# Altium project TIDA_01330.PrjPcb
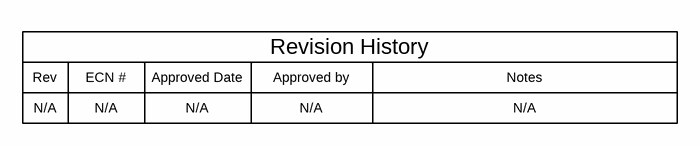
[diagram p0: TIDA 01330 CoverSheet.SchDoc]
CopyrightYear: 2016; EVM_Orderable: N/A; PCB_Rev: E1; PRJ_Customer: Public Release; PRJ_Engineer: Clark Kinnaird; PRJ_Number: TIDA-01330; PRJ_Title: Automotive 2-Axis Power Seat Driver; SCH_Rev: E1; TechSupport: http://www.ti.com/support; TID: TIDA-01330
3 sheets, 85 parts. Net scope: global (net labels, ports and power ports of the same name join across sheets).
Board file: TIDA-01330.PcbDoc
Sheets:
  TIDA 01330 CoverSheet.SchDoc
  TIDA 01330 Schematic.SchDoc
  TID_Hardware.SchDoc

## Sheet TIDA 01330 CoverSheet.SchDoc
size 431 x 279 mm; Date: Not shown in title block; ApprovedBy: Not shown in title block; CheckedBy: Not shown in title block; Author: Not shown in title block; CompanyName: Not shown in title block; Engineer: Not shown in title block; Organization: Not shown in title block; Address1: Not shown in title block; Address2: Not shown in title block; Address3: Not shown in title block; Address4: Not shown in title block; DocumentNumber: 1; Revision: Use project parameter SCH_Rev; SheetNumber: 1; SheetTotal: 3; PageSetup: Record=PageOptions¦CenterHorizontal=True¦CenterVertical=True¦PrintScale=1.00¦XCorrection=1.00¦YCorrection=1.00¦PrintKind=0¦BorderSize=5000000¦LeftOffset=0¦BottomOffset=0¦Orientation=2¦PaperLength=1000¦PaperWidth=1000¦Scale=100¦PaperSource=15¦PrintQuality=600¦MediaType=1¦DitherType=10¦PaperKind=Letter¦PrintScaleMode=1

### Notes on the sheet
- Rev
- N/A
- ECN #
- Approved Date
- Approved by
- Revision History
- Notes

## Sheet TIDA 01330 Schematic.SchDoc
size 431 x 279 mm; Date: Not shown in title block; ApprovedBy: Not shown in title block; CheckedBy: Not shown in title block; Author: Not shown in title block; CompanyName: Not shown in title block; Engineer: Not shown in title block; Organization: Not shown in title block; Address1: Not shown in title block; Address2: Not shown in title block; Address3: Not shown in title block; Address4: Not shown in title block; DocumentNumber: 1; Revision: Use project parameter SCH_Rev; SheetNumber: 2; SheetTotal: 2; PageSetup: Record=PageOptions¦CenterHorizontal=True¦CenterVertical=True¦PrintScale=0.98¦XCorrection=1.00¦YCorrection=1.00¦PrintKind=0¦BorderSize=5000000¦LeftOffset=0¦BottomOffset=0¦Orientation=2¦PaperLength=4318¦PaperWidth=2794¦Scale=100¦PaperSource=15¦PrintQuality=-3¦MediaType=1¦DitherType=10¦PrintScaleMode=1¦PaperKind=11x17¦PaperIndex=17
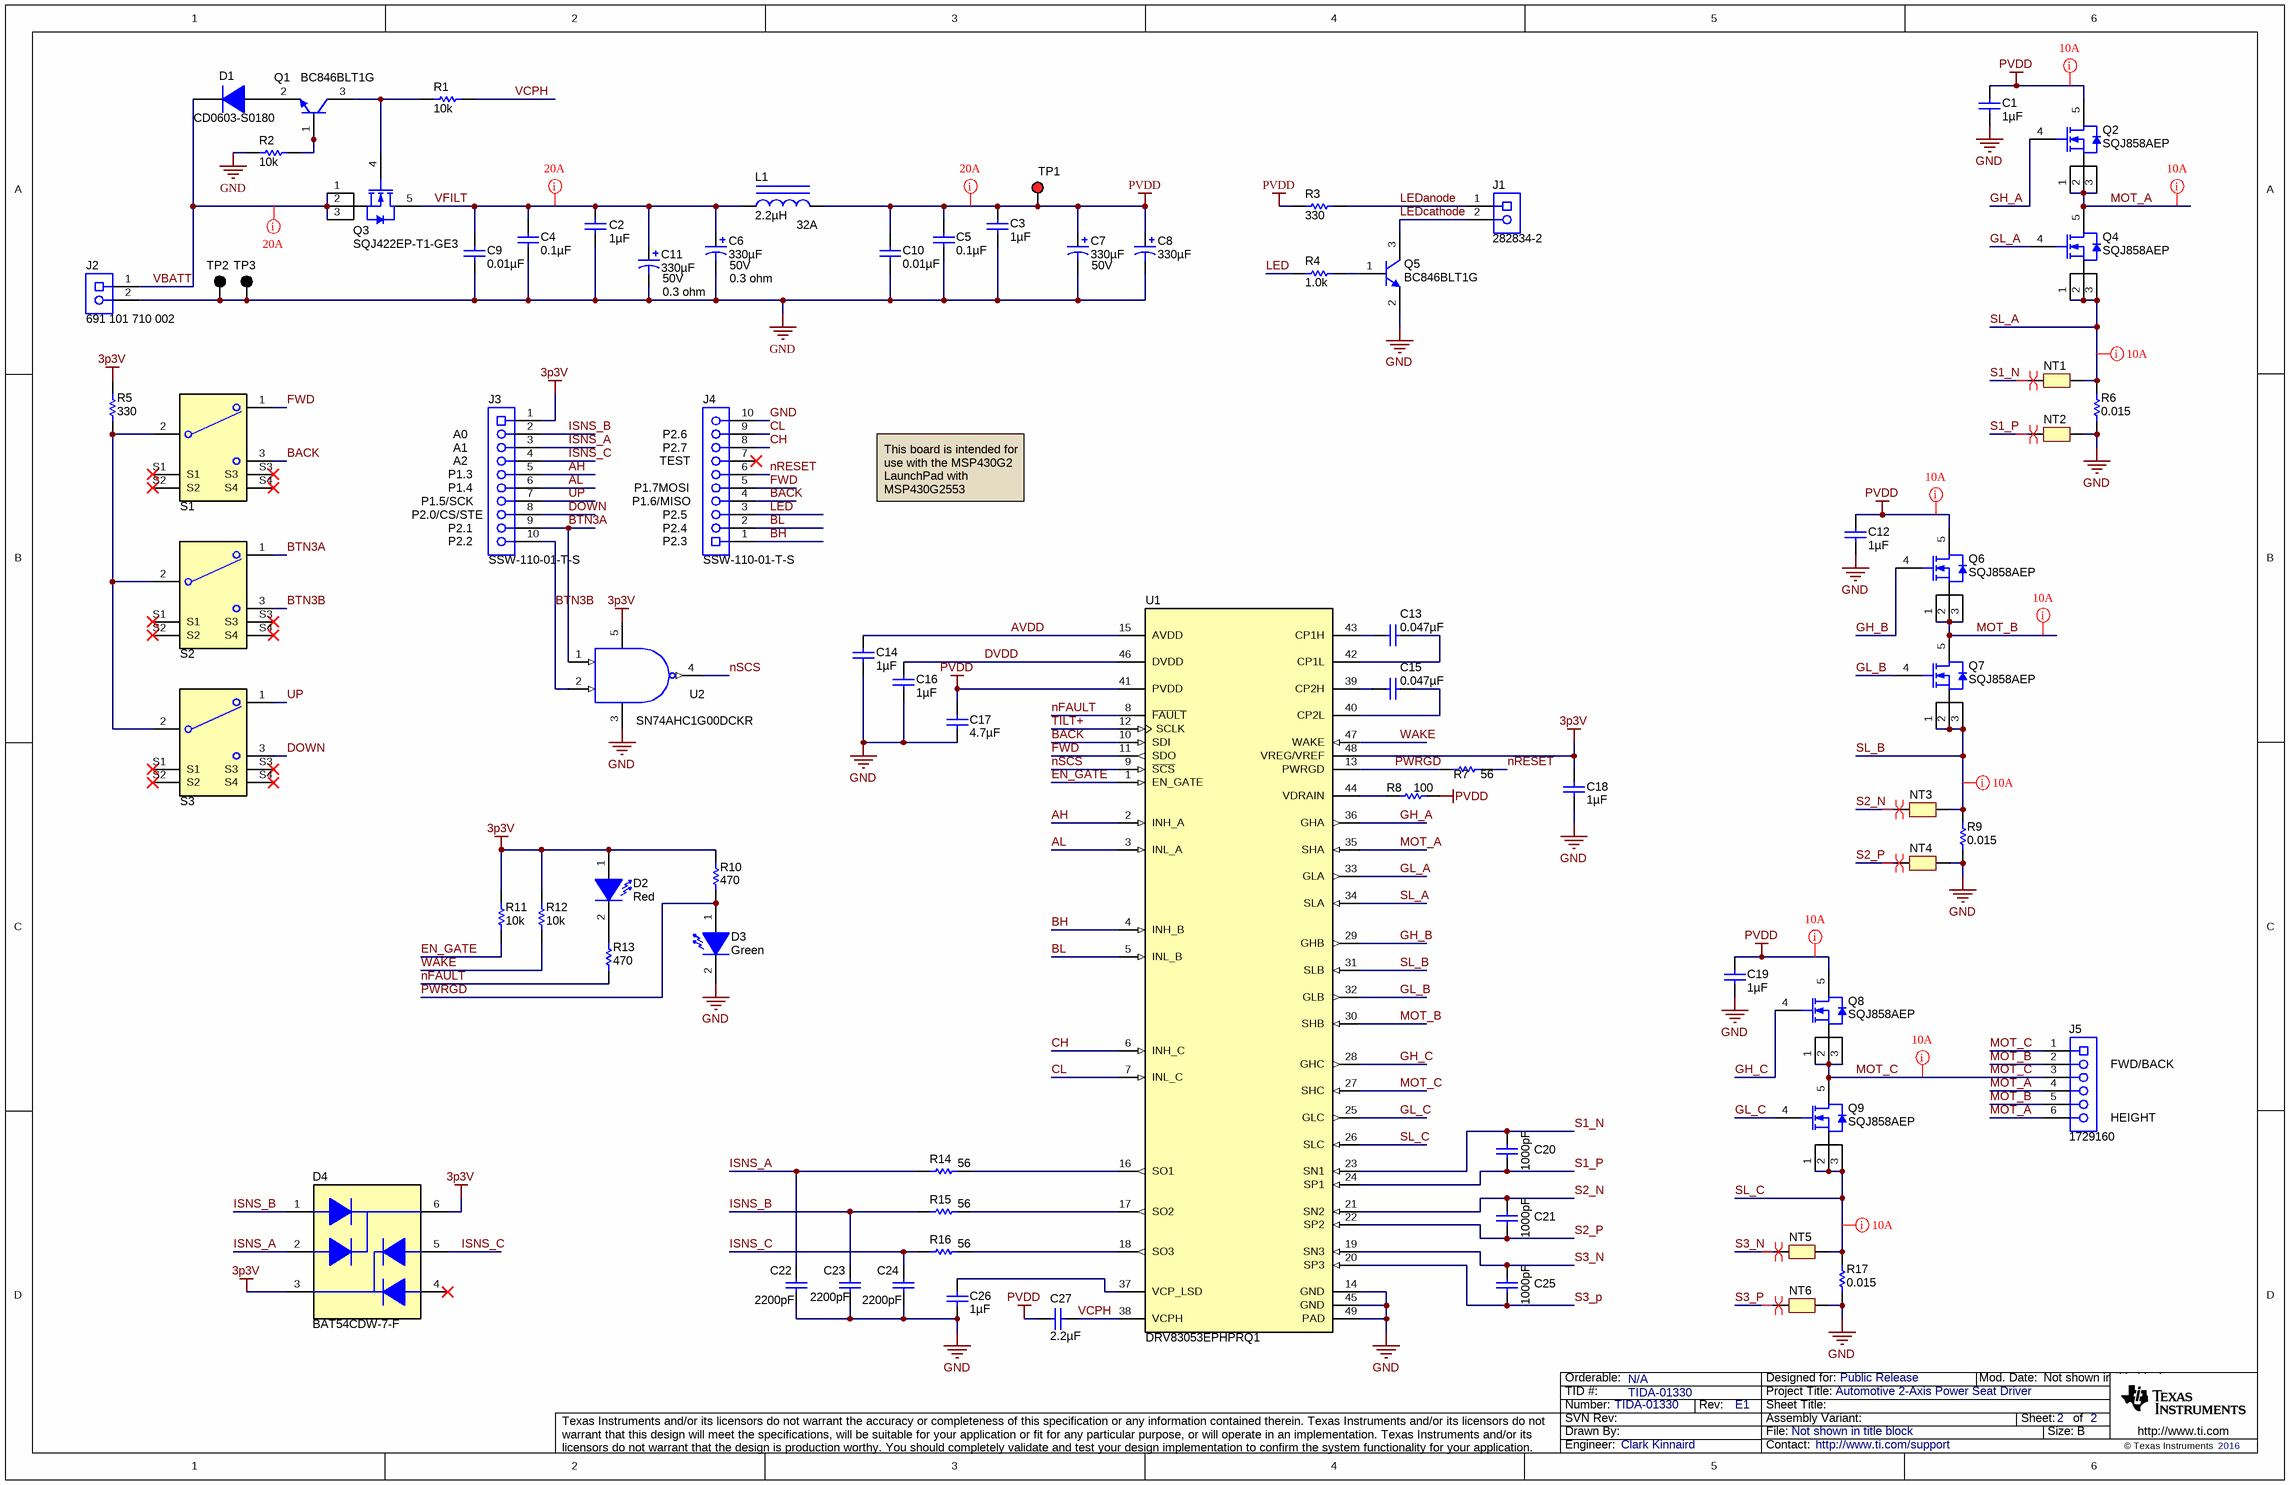
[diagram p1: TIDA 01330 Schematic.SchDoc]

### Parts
C1  ValueDisplayed: 1µF  [0603L]  (hidden comment: UMK107AB7105KA-T)
C2  ValueDisplayed: 1µF  [0805L]  (hidden comment: GRM21BR71H105KA12L)
C3  ValueDisplayed: 1µF  [0805L]  (hidden comment: GRM21BR71H105KA12L)
C4  ValueDisplayed: 0.1µF  [0603]  (hidden comment: C1608X7R1H104K080AA)
C5  ValueDisplayed: 0.1µF  [0603]  (hidden comment: C1608X7R1H104K080AA)
C6  ValueDisplayed: 330µF  Value1: 0.3 ohm  Value2: 50V  [SM_RADIAL_G]  (hidden comment: EEE-FT1H331AP)
C7  ValueDisplayed: 330µF  Value2: 50V  [SM_RADIAL_G]  (hidden comment: EEE-FT1H331AP)
C8  ValueDisplayed: 330µF  [SM_RADIAL_G]  (hidden comment: EEE-FT1H331AP)
C9  ValueDisplayed: 0.01µF  [0603]  (hidden comment: C1608X7R1H103K080AA)
C10  ValueDisplayed: 0.01µF  [0603]  (hidden comment: C1608X7R1H103K080AA)
C11  ValueDisplayed: 330µF  Value1: 0.3 ohm  Value2: 50V  [SM_RADIAL_G]  (hidden comment: EEE-FT1H331AP)
C12  ValueDisplayed: 1µF  [0603L]  (hidden comment: UMK107AB7105KA-T)
C13  ValueDisplayed: 0.047µF  [0603L]  (hidden comment: C0603C473K1RACTU)
C14  ValueDisplayed: 1µF  [0603]  (hidden comment: C1608X7R1C105K080AC)
C15  ValueDisplayed: 0.047µF  [0603L]  (hidden comment: C0603C473K1RACTU)
C16  ValueDisplayed: 1µF  [0603]  (hidden comment: C1608X7R1C105K080AC)
C17  ValueDisplayed: 4.7µF  [1206_180]  (hidden comment: GRM31CR71H475KA12L)
C18  ValueDisplayed: 1µF  [0603]  (hidden comment: C1608X7R1C105K080AC)
C19  ValueDisplayed: 1µF  [0603L]  (hidden comment: UMK107AB7105KA-T)
C20  ValueDisplayed: 1000pF  [0603L]  (hidden comment: GRM188R71C102KA01D)
C21  ValueDisplayed: 1000pF  [0603L]  (hidden comment: GRM188R71C102KA01D)
C22  ValueDisplayed: 2200pF  [0603L]  (hidden comment: GRM188R71C222KA01D)
C23  ValueDisplayed: 2200pF  [0603L]  (hidden comment: GRM188R71C222KA01D)
C24  ValueDisplayed: 2200pF  [0603L]  (hidden comment: GRM188R71C222KA01D)
C25  ValueDisplayed: 1000pF  [0603L]  (hidden comment: GRM188R71C102KA01D)
C26  ValueDisplayed: 1µF  [0603]  (hidden comment: C1608X7R1C105K080AC)
C27  ValueDisplayed: 2.2µF  [1210_270]  (hidden comment: GRM32ER72A225KA35L)
D1  CD0603-S0180  [Diode_0603]
D2  value Red  [LED_LTST-C170_Red]  (hidden comment: LTST-C170KRKT)
D3  value Green  [LTST-C170KGKT_Green]  (hidden comment: LTST-C170KGKT)
D4  BAT54CDW-7-F  [SOT-363]
J1  282834-2  [TEC_282834-2]
J2  691 101 710 002  [Wurth_691101710002]
J3  SSW-110-01-T-S  [Samtec_SSW-110-x1-x-S]
J4  SSW-110-01-T-S  [Samtec_SSW-110-x1-x-S]
J5  1729160  [Phoenix_1729160]
L1  ValueDisplayed: 2.2µH  Value2: 32A  [XAL1010]  (hidden comment: XAL1010-222MEB)
NT1  Net-Tie  [Net-Tie_10mil]  (value not drawn)  (net tie, no BOM)
NT2  Net-Tie  [Net-Tie_10mil]  (value not drawn)  (net tie, no BOM)
NT3  Net-Tie  [Net-Tie_10mil]  (value not drawn)  (net tie, no BOM)
NT4  Net-Tie  [Net-Tie_10mil]  (value not drawn)  (net tie, no BOM)
NT5  Net-Tie  [Net-Tie_10mil]  (value not drawn)  (net tie, no BOM)
NT6  Net-Tie  [Net-Tie_10mil]  (value not drawn)  (net tie, no BOM)
Q1  BC846BLT1G  [SOT-23]
Q2  SQJ858AEP  [PowerPAK_SO-8L]
Q3  SQJ422EP-T1-GE3  [PowerPAK_SO-8L]
Q4  SQJ858AEP  [PowerPAK_SO-8L]
Q5  BC846BLT1G  [SOT-23]
Q6  SQJ858AEP  [PowerPAK_SO-8L]
Q7  SQJ858AEP  [PowerPAK_SO-8L]
Q8  SQJ858AEP  [PowerPAK_SO-8L]
Q9  SQJ858AEP  [PowerPAK_SO-8L]
R1  ValueDisplayed: 10k  [0402]  (hidden comment: CRCW040210K0JNED)
R2  ValueDisplayed: 10k  [0402]  (hidden comment: CRCW040210K0JNED)
R3  ValueDisplayed: 330  [1206]  (hidden comment: CRCW1206330RJNEA)
R4  ValueDisplayed: 1.0k  [0402]  (hidden comment: CRCW04021K00JNED)
R5  ValueDisplayed: 330  [0402]  (hidden comment: CRCW0402330RJNED)
R6  ValueDisplayed: 0.015  [2512]  (hidden comment: CRA2512-FZ-R015ELF)
R7  ValueDisplayed: 56  [0402]  (hidden comment: CRCW040256R0JNED)
R8  ValueDisplayed: 100  [0402]  (hidden comment: CRCW0402100RFKED)
R9  ValueDisplayed: 0.015  [2512]  (hidden comment: CRA2512-FZ-R015ELF)
R10  ValueDisplayed: 470  [0402]  (hidden comment: CRCW0402470RJNED)
R11  ValueDisplayed: 10k  [0402]  (hidden comment: CRCW040210K0JNED)
R12  ValueDisplayed: 10k  [0402]  (hidden comment: CRCW040210K0JNED)
R13  ValueDisplayed: 470  [0402]  (hidden comment: CRCW0402470RJNED)
R14  ValueDisplayed: 56  [0402]  (hidden comment: CRCW040256R0JNED)
R15  ValueDisplayed: 56  [0402]  (hidden comment: CRCW040256R0JNED)
R16  ValueDisplayed: 56  [0402]  (hidden comment: CRCW040256R0JNED)
R17  ValueDisplayed: 0.015  [2512]  (hidden comment: CRA2512-FZ-R015ELF)
S1  7105J3V3QE2  [SW_710XJ3V3]  (value not drawn)
S2  7105J3V3QE2  [SW_710XJ3V3]  (value not drawn)
S3  7105J3V3QE2  [SW_710XJ3V3]  (value not drawn)
TP1  5005  [Keystone5005]  (value not drawn)
TP2  5006  [Keystone5006]  (value not drawn)
TP3  5006  [Keystone5006]  (value not drawn)
U1  DRV83053EPHPRQ1  [PHP0048G_N]
U2  SN74AHC1G00DCKR  [DCK0005A_N]

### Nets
3p3V: C18.2 D2.1(A) D4.3(C2) D4.6(C1) J3.1 R5.1 R10.2 R11.2 R12.2 U1.48(VREG/VREF) U2.5(VCC)
GND: C1.2 C2.2 C3.2 C4.2 C5.2 C6.2(-) C7.2(-) C8.2(-) C9.2 C10.2 C11.2(-) C12.2 C14.1 C16.1 C17.2 C18.1 C19.2 C22.2 C23.2 C24.2 C26.2 D3.2(K) J2.2 J4.10 NT2.2 NT4.2 NT6.2 Q5.2(E) R2.2 R6.1 R9.1 R17.1 TP2.1 TP3.1 U1.14(GND) U1.45(GND) U1.49(PAD) U2.3(GND)
PVDD: C1.1 C3.1 C5.1 C7.1(+) C8.1(+) C10.1 C12.1 C17.1 C19.1 C27.2 L1.2 Q2.5(D) Q6.5(D) Q8.5(D) R3.1 R8.2 TP1.1 U1.41(PVDD)
AH: J3.5 U1.2(INH_A)
AL: J3.6 U1.3(INL_A)
AVDD: C14.2 U1.15(AVDD)
BACK: J4.4 S1.3 U1.10(SDI)
BH: J4.1 U1.4(INH_B)
BL: J4.2 U1.5(INL_B)
BTN3A: J3.9 S2.1 U2.1(A)
BTN3B: J3.10 S2.3 U2.2(B)
CH: J4.8 U1.6(INH_C)
CL: J4.9 U1.7(INL_C)
DOWN: J3.8 S3.3
DVDD: C16.2 U1.46(DVDD)
EN_GATE: R11.1 U1.1(EN_GATE)
FWD: J4.5 S1.1 U1.11(SDO)
GH_A: Q2.4(G) U1.36(GHA)
GH_B: Q6.4(G) U1.29(GHB)
GH_C: Q8.4(G) U1.28(GHC)
GL_A: Q4.4(G) U1.33(GLA)
GL_B: Q7.4(G) U1.32(GLB)
GL_C: Q9.4(G) U1.25(GLC)
ISNS_A: C22.1 D4.2(A1) J3.3 R14.1
ISNS_B: C23.1 D4.1(A1) J3.2 R15.1
ISNS_C: C24.1 D4.5(A2) J3.4 R16.1
LED: J4.3 R4.1
LEDanode: J1.1 R3.2
LEDcathode: J1.2 Q5.3(C)
MOT_A: J5.4 J5.6 Q2.1(S) Q2.2(S) Q2.3(S) Q4.5(D) U1.35(SHA)
MOT_B: J5.2 J5.5 Q6.1(S) Q6.2(S) Q6.3(S) Q7.5(D) U1.30(SHB)
MOT_C: J5.1 J5.3 Q8.1(S) Q8.2(S) Q8.3(S) Q9.5(D) U1.27(SHC)
nFAULT: R13.1 U1.8(~{FAULT})
nRESET: J4.6 R7.2
nSCS: U1.9(~{SCS}) U2.4(Y)
PWRGD: D3.1(A) R7.1 R10.1 U1.13(PWRGD)
S1_N: C20.1 NT1.1 U1.23(SN1)
S1_P: C20.2 NT2.1 U1.24(SP1)
S2_N: C21.1 NT3.1 U1.21(SN2)
S2_P: C21.2 NT4.1 U1.22(SP2)
S3_N: C25.1 NT5.1 U1.19(SN3)
S3_p: C25.2 NT6.1 U1.20(SP3)
SL_A: NT1.2 Q4.1(S) Q4.2(S) Q4.3(S) R6.2 U1.34(SLA)
SL_B: NT3.2 Q7.1(S) Q7.2(S) Q7.3(S) R9.2 U1.31(SLB)
SL_C: NT5.2 Q9.1(S) Q9.2(S) Q9.3(S) R17.2 U1.26(SLC)
TILT+: U1.12(SCLK)
UP: J3.7 S3.1
VBATT: D1.1(K) J2.1 Q3.1(S) Q3.2(S) Q3.3(S)
VCPH: C27.1 R1.1 U1.38(VCPH)
VFILT: C2.1 C4.1 C6.1(+) C9.1 C11.1(+) L1.1 Q3.5(D)
WAKE: R12.1 U1.47(WAKE)
NetC13_1: C13.1 U1.43(CP1H)
NetC13_2: C13.2 U1.42(CP1L)
NetC15_1: C15.1 U1.39(CP2H)
NetC15_2: C15.2 U1.40(CP2L)
NetC26_1: C26.1 U1.37(VCP_LSD)
NetD1_2: D1.2(A) Q1.2(E)
NetD2_2: D2.2(K) R13.2
NetQ1_1: Q1.1(B) R2.1
NetQ1_3: Q1.3(C) Q3.4(G) R1.2
NetQ5_1: Q5.1(B) R4.2
NetR5_2: R5.2 S1.2(COM) S2.2(COM) S3.2(COM)
NetR8_1: R8.1 U1.44(VDRAIN)
NetR14_2: R14.2 U1.16(SO1)
NetR15_2: R15.2 U1.17(SO2)
NetR16_2: R16.2 U1.18(SO3)

Not connected (* = marked no-connect by the designer): D4 4(A2)*; J4 7*; S1 S1* S2* S3* S4*; S2 S1* S2* S3* S4*; S3 S1* S2* S3* S4*

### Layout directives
rule Undefined: MOT_A, MOT_B, MOT_C, PVDD, SL_A, SL_B, SL_C, VBATT, VFILT
differential pair: S1_N, S1_P, S2_N, S2_P, S3_N, S3_p

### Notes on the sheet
- (near J3) A0
- (near J4) P2.6
- (near J3) P1.5/SCK
- (near J3) A1
- (near J3) A2
- (near J3) P1.3
- (near J3) P1.4
- (near J4) P1.7MOSI
- (near J4) P1.6/MISO
- (near J4) TEST
- (near J4) P2.7
- This board is intended for use with the MSP430G2 LaunchPad with MSP430G2553
- (near J3) P2.0/CS/STE
- (near J3) P2.1
- (near J3) P2.2
- (near J4) P2.5
- (near J4) P2.4
- (near J4) P2.3
- (near J5) FWD/BACK
- (near J5) HEIGHT

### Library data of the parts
C1 C12 C19 = UMK107AB7105KA-T: CAP, CERM, 1 µF, 50 V, +/- 10%, X7R, 0603; Manufacturer: Taiyo Yuden; Polarized: N; CompType: Capacitor; Value: 1uF; U/M: EA; Cap_F: 0.000001; Tolerance_%: 10; Value1: Unknown; VDC_V: 50; Value2: 50V; TaMin_C: -55; TaMax_C: 125; Cap_Case: 0603
C2 C3 = GRM21BR71H105KA12L: CAP, CERM, 1uF, 50V, +/-10%, X7R, 0805; Manufacturer: MuRata; Polarized: N; CompType: Capacitor; U/M: EA; Cap_F: 0.000001; Tolerance_%: 10; Value1: Unknown; VDC_V: 50; TaMin_C: -55; TaMax_C: 125; Cap_Case: 0805
C4 C5 = C1608X7R1H104K080AA: CAP, CERM, 0.1 µF, 50 V, +/- 10%, X7R, 0603; Manufacturer: TDK; Polarized: N; CompType: Capacitor; Value: 0.1uF; U/M: EA; Cap_F: 0.0000001; Tolerance_%: 10; ESR_ohm: 0.0296; Value1: 0.0296 ohm; VDC_V: 50; Value2: 50V; IRMS_A: 0.97199; TaMin_C: -55; TaMax_C: 125; SizeArea_mm2: 1.28; SizeAreaWB_mm2: 4.68; SizeX_mm: 1.6; SizeY_mm: 0.8; SizeZ_mm: 1; AEC Category: Q200
C6 C11 = EEE-FC1H221P: CAP, AL, 330 µF, 50 V, +/- 20%, 0.3 ohm, SMD; Manufacturer: Panasonic; Polarized: Y; CompType: Capacitor; Value: 330uF; U/M: EA; Cap_F: 0.00033; Tolerance_%: 20; VDC_V: 50; ESR_ohm: 0.3; IRMS_A: 0.5; TaMin_C: -40; TaMax_C: 105; Cap_Case: G
C7 = EEE-FC1H221P: CAP, AL, 330 µF, 50 V, +/- 20%, 0.3 ohm, SMD; Manufacturer: Panasonic; Polarized: Y; CompType: Capacitor; Value: 330uF; U/M: EA; Cap_F: 0.00033; Tolerance_%: 20; Value1: 0.3 ohm; VDC_V: 50; ESR_ohm: 0.3; IRMS_A: 0.5; TaMin_C: -40; TaMax_C: 105; Cap_Case: G
C8 = EEE-FC1H221P: CAP, AL, 330 µF, 50 V, +/- 20%, 0.3 ohm, SMD; Manufacturer: Panasonic; Polarized: Y; CompType: Capacitor; Value: 330uF; U/M: EA; Cap_F: 0.00033; Tolerance_%: 20; Value1: 0.3 ohm; VDC_V: 50; Value2: 50V; ESR_ohm: 0.3; IRMS_A: 0.5; TaMin_C: -40; TaMax_C: 105; Cap_Case: G
C9 C10 = C1608X7R1H103K080AA: CAP, CERM, 0.01 µF, 50 V, +/- 10%, X7R, 0603; Manufacturer: TDK; Polarized: N; CompType: Capacitor; Value: 0.01uF; U/M: EA; Cap_F: 0.00000001; Tolerance_%: 10; ESR_ohm: 0.0539; Value1: 0.0539 ohm; VDC_V: 50; Value2: 50V; TaMin_C: -55; TaMax_C: 125; SizeArea_mm2: 1.28; SizeAreaWB_mm2: 4.68; SizeX_mm: 1.6; SizeY_mm: 0.8; SizeZ_mm: 1; AEC Category: Q200
C13 C15 = GRM188R72A104KA35D: CAP, CERM, 0.047uF, 100V, +/-10%, X7R, 0603; Manufacturer: Kemet; Polarized: N; CompType: Capacitor; U/M: EA; Cap_F: 0.000000047; Tolerance_%: 10; Value1: Unknown; VDC_V: 100; TaMin_C: -55; TaMax_C: 125; Cap_Case: 0603
C14 C16 C18 C26 = C1608X7R1C105K080AC: CAP, CERM, 1 µF, 16 V, +/- 10%, X7R, 0603; Manufacturer: TDK; Polarized: N; CompType: Capacitor; Value: 1uF; U/M: EA; Cap_F: 0.000001; Tolerance_%: 10; ESR_ohm: 0.0057; Value1: 0.0057 ohm; VDC_V: 16; Value2: 16V; TaMin_C: -55; TaMax_C: 125; SizeArea_mm2: 1.28; SizeAreaWB_mm2: 4.68; SizeX_mm: 1.6; SizeY_mm: 0.8; SizeZ_mm: 1; AEC Category: Q200
C17 = GRM31CR71H475KA12L: CAP, CERM, 4.7 µF, 50 V, +/- 10%, X7R, 1206; Manufacturer: MuRata; Polarized: N; CompType: Capacitor; Value: 4.7uF; U/M: EA; Cap_F: 0.0000047; Tolerance_%: 10; Value1: Unknown; VDC_V: 50; Value2: 50V; TaMin_C: -55; TaMax_C: 125; Cap_Case: 2220; SizeArea_mm2: 5.12; SizeAreaWB_mm2: 10.92; SizeX_mm: 3.2; SizeY_mm: 1.6; SizeZ_mm: 1.8; AEC Category: Q200
C20 C21 C25 = GRM188R71C102KA01D: CAP, CERM, 1000pF, 16V, +/-10%, X7R, 0603; Manufacturer: MuRata; Polarized: N; CompType: Capacitor; U/M: EA; Cap_F: 0.000000001; Tolerance_%: 10; Value1: Unknown; VDC_V: 16; TaMin_C: -55; TaMax_C: 125; Cap_Case: 0603
C22-C24 = GRM188R71C222KA01D: CAP, CERM, 2200pF, 16V, +/-10%, X7R, 0603; Manufacturer: MuRata; Polarized: N; CompType: Capacitor; U/M: EA; Cap_F: 0.0000000022; Tolerance_%: 10; Value1: Unknown; VDC_V: 16; TaMin_C: -55; TaMax_C: 125; Cap_Case: 0603
C27 = GRM32ER72A225KA35L: CAP, CERM, 2.2 µF, 100 V, +/- 10%, X7R, 1210; Manufacturer: MuRata; Polarized: N; CompType: Capacitor; Value: 2.2uF; U/M: EA; Cap_F: 0.0000022; Tolerance_%: 10; ESR_ohm: 0.007; Value1: 0.007 ohm; VDC_V: 100; Value2: 100V; IRMS_A: 4.4; TaMin_C: -55; TaMax_C: 125; Cap_Case: 1210; SizeArea_mm2: 8; SizeAreaWB_mm2: 14.7; SizeX_mm: 3.2; SizeY_mm: 2.5; SizeZ_mm: 2.7; AEC Category: Q200
D1 = CD0603-S0180: Diode, Switching, 90V, 0.1A, 0603 Diode; Manufacturer: Bourns; U/M: EA; Vf_V: 1; Value2: 1V; Io_A: 0.1; Vr_V: 90; TJmax_C: 125
D2 = LTST-C170KRKT: LED, Red, SMD; Manufacturer: Lite-On; Type: AlInGaP; Vf_V: 2; Value2: 2V; Io_A: 0.02; Value1: W; SizeAreaWB_mm2: 6.75; SizeArea_mm2: 2.5; SizeY_mm: 1.25; SizeZ_mm: 1.2; U/M: EA
D3 = LTST-C170KGKT: LED, Green, SMD; Manufacturer: Lite-On; Type: AlInGaP; Vf_V: 2; Value2: 2V; Io_A: 0.02; Value1: W; U/M: EA
D4 = BAT54CDW-7-F: Diode, Schottky, 30 V, 0.2 A, SOT-363; Manufacturer: Diodes Inc.; SymbolCreator: Altium; U/M: EA; Vf_V: 1; Value: 30V; Value1: 0.2A; Value2: 1V; Io_A: 0.2; Vr_V: 30; TJmax_C: 125; AEC Category: Q101; AEC Qualified: N
J1 = 282834-2: Terminal Block, 2x1, 2.54mm, TH; Manufacturer: TE Connectivity; SymbolCreator: a0412235
J2 = 691 101 710 002: Terminal Block, 5 mm, 2x1, Tin, TH; Manufacturer: Wurth Elektronik; SymbolCreator: a0412235
J3 J4 = SSW-110-01-T-S: Receptacle, 2.54mm, 10x1, Tin, TH; Manufacturer: Samtec; SymbolCreator: a0411947; Pitch_mm: 2.54; Gender: Female; Row_Count: 1; Cert_CSA: Y
J5 = 1729160: Terminal Block, 6x1, 5.08mm, Th; Manufacturer: Phoenix Contact; SymbolCreator: a0411947
L1 = XAL1010-222MEB: Inductor, Shielded, Composite, 2.2 µH, 32 A, 0.00255 ohm, SMD; Manufacturer: Coilcraft; Value: 2.2uH; Ind_H: 2.2E-6; Imax_A: 32; Irms: 32A @ 40C rise; Isat: 34A @ 30% inductance drop; AEC Category: Q200
NT1-NT6 = Net-Tie: Single point connection between nets.; SymbolCreator: codlsc
Q1 Q5 = BC846BLT1G, ON Semiconductor: Transistor, NPN, 65V, 0.1A, SOT-23; CompType: BJT; PNP: 0; NPN: 1; Vceo_V: 65; Vcesat1_V: 0.7; Value: 0.7V; IcRated_A: 0.1; HfeMax: 450; TaMin_C: -55; TaMax_C: 150; U/M: EA
Q2 Q4 Q6-Q9 = SQJ858AEP-T1-GE3: MOSFET, N-CH, 40 V, 58 A, PowerPAK_SO-8L; Manufacturer: Vishay-Siliconix; Alternate Manufacturer: None; SymbolCreator: a0412235; U/M: EA; ChType: N; Value: 40V; VdsMax_V: 40; Value1: 0.0075 ohm; Rdson45_ohm: 0.0075; Value2: 36 nC; QgTyp_nC: 36; Vgs_V: 20; IdsMax_A: 58; AEC Category: Q101
Q3 = SQJ422EP-T1-GE3: MOSFET, N-CH, 40 V, 75 A, PowerPAK_SO-8L; Manufacturer: Vishay-Siliconix; Alternate Manufacturer: None; SymbolCreator: a0412235; U/M: EA; ChType: N; Value: 40V; VdsMax_V: 40; Value1: 0.0043 ohm; Rdson45_ohm: 0.0043; Value2: 67 nC; QgTyp_nC: 67; Vgs_V: 20; IdsMax_A: 75; AEC Category: Q101
R1 R2 R11 R12 = CRCW040210K0JNED: RES, 10 k, 5%, 0.063 W, 0402; Manufacturer: Vishay-Dale; CompType: Resistor; Value: 10k; Res_ohm: 10000; Value_Code: 10k0; Tolerance_%: 5; Power_W: 0.063; Value2: 0.063W; VDC_V: 50; TempCo: 200 ppm/C; EIA_Code: E24; U/M: EA; AEC Category: Q200
R3 = CRCW1206330RJNEA: RES, 330, 5%, 0.25 W, 1206; Manufacturer: Vishay-Dale; CompType: Resistor; Value: 330; Value_Code: 330R; Tolerance_%: 5; Power_W: 0.25; Value2: 0.25W; VDC_V: 200; TempCo: 200 ppm/C; SizeArea_mm2: 5.12; SizeX_mm: 3.2; SizeY_mm: 1.6; SizeZ_mm: 1.35; EIA_Code: E24; U/M: EA; AEC Category: Q200
R4 = CRCW04021K00JNED: RES, 1.0 k, 5%, 0.063 W, 0402; Manufacturer: Vishay-Dale; CompType: Resistor; Value: 1.0k; Res_ohm: 1000; Value_Code: 1k00; Tolerance_%: 5; Power_W: 0.063; Value2: 0.063W; VDC_V: 50; TempCo: 200 ppm/C; SizeArea_mm2: 0.5; SizeX_mm: 1; SizeZ_mm: 0.6; EIA_Code: E24; U/M: EA; AEC Category: Q200
R5 = CRCW0402330RJNED: RES, 330, 5%, 0.063 W, 0402; Manufacturer: Vishay-Dale; CompType: Resistor; Value: 330; Value_Code: 330R; Tolerance_%: 5; Power_W: 0.063; Value2: 0.063W; VDC_V: 50; TempCo: 200 ppm/C; EIA_Code: E24; U/M: EA; AEC Category: Q200
R6 R9 R17 = CRA2512-FZ-R015ELF: RES, 0.015, 1%, 3 W, 2512; Manufacturer: Bourns; CompType: Resistor; Value: 0.015; Value_Code: R015; Tolerance_%: 1; Power_W: 3; Value2: 3W; TempCo: 75 ppm/C; SizeArea_mm2: 20.16; SizeX_mm: 6.3; SizeY_mm: 3.2; SizeZ_mm: 0.71; EIA_Code: E96; U/M: EA; AEC Category: Q200
R7 R14-R16 = CRCW040256R0JNED: RES, 56, 5%, 0.063 W, 0402; Manufacturer: Vishay-Dale; CompType: Resistor; Value: 56; Value_Code: 56R0; Tolerance_%: 5; Power_W: 0.063; Value2: 0.063W; VDC_V: 50; TempCo: 200 ppm/C; EIA_Code: E24; U/M: EA; AEC Category: Q200
R8 = CRCW0402100RFKED: RES, 100, 1%, 0.063 W, 0402; Manufacturer: Vishay-Dale; CompType: Resistor; Value: 100; Value_Code: 100R; Tolerance_%: 1; Power_W: 0.063; Value2: 0.063W; VDC_V: 50; TempCo: 100 ppm/C; EIA_Code: E96; U/M: EA; AEC Category: Q200
R10 R13 = CRCW0402470RJNED: RES, 470, 5%, 0.063 W, 0402; Manufacturer: Vishay-Dale; CompType: Resistor; Value: 470; Value_Code: 470R; Tolerance_%: 5; Power_W: 0.063; Value2: 0.063W; VDC_V: 50; TempCo: 200 ppm/C; SizeArea_mm2: 0.5; SizeX_mm: 1; SizeZ_mm: 0.6; EIA_Code: E24; U/M: EA; AEC Category: Q200
S1-S3 = 7105J3V3QE2: Switch, SPDT, Mom-Off-Mom, 3 Pos, 5 A, 28 VDC, TH; Manufacturer: C&K Components; SymbolCreator: Altium; VDC_V: 28; PositionCount: 3; CurrentRating_mA: 5000
TP1 = 5005: Test Point, Compact, Red, TH; Manufacturer: Keystone; CompType: Test Point Loop; U/M: EA
TP2 TP3 = 5006: Test Point, Compact, Black, TH; Manufacturer: Keystone; CompType: Test Point Loop; U/M: EA
U1 = DRV83053EPHPRQ1: Three Phase Automotive Gate Driver with Three Integrated Current Shunt Amplifiers and Voltage Regulator, PHP0048G; Alternate PartNumber: DRV83053EPHPQ1; Manufacturer: Texas Instruments; SymbolCreator: Altium; SizeArea_mm2: 81; SizeAreaWB_mm2: 121; SizeX_mm: 9; SizeZ_mm: 1.2; CompType: IC; U/M: EA
U2 = SN74AHC1G00DCKR: SINGLE 2-INPUT POSITIVE-NAND GATE, DCK0005A (SOT-5); Alternate PartNumber: SN74AHC1G00DCKT; Manufacturer: Texas Instruments; SymbolCreator: a0411947; SizeArea_mm2: 4.2; SizeAreaWB_mm2: 9.3; SizeX_mm: 2.1; SizeY_mm: 2; SizeZ_mm: 1.1; CompType: IC; U/M: EA

## Sheet TID_Hardware.SchDoc
size 431 x 279 mm; Date: Not shown in title block; ApprovedBy: Not shown in title block; CheckedBy: Not shown in title block; Author: Not shown in title block; CompanyName: Not shown in title block; Engineer: Not shown in title block; Organization: Not shown in title block; Address1: Not shown in title block; Address2: Not shown in title block; Address3: Not shown in title block; Address4: Not shown in title block; DocumentNumber: 1; Revision: Use project parameter SCH_Rev; SheetNumber: 3; SheetTotal: 3; PageSetup: Record=PageOptions¦CenterHorizontal=True¦CenterVertical=True¦PrintScale=1.00¦XCorrection=1.00¦YCorrection=1.00¦PrintKind=0¦BorderSize=5000000¦LeftOffset=0¦BottomOffset=0¦Orientation=2¦PaperLength=1000¦PaperWidth=1000¦Scale=100¦PaperSource=15¦PrintQuality=600¦MediaType=1¦DitherType=10¦PaperKind=Letter¦PrintScaleMode=1
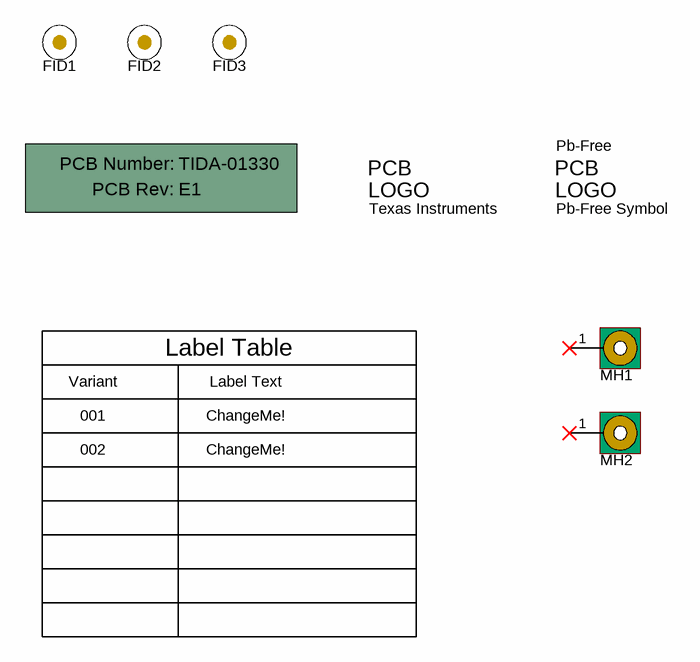
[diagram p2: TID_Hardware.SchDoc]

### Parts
!PCB?  Printed Circuit Board  (value not drawn)  (mechanical)
FID1  Fiducial  [Fiducial10-20]  (value not drawn)
FID2  Fiducial  [Fiducial10-20]  (value not drawn)
FID3  Fiducial  [Fiducial10-20]  (value not drawn)
Logo1  Texas Instruments  [TI_Stacked_Overlay_Small]  (no BOM)
MH1  MTG_Pads  [MTGP_6-32_Washer]  (value not drawn)  (no BOM)
MH2  MTG_Pads  [MTGP_6-32_Washer]  (value not drawn)  (no BOM)
Pb-Free  Pb-Free Symbol  [Pb-Free_Overlay_Small]  (no BOM)

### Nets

Not connected (* = marked no-connect by the designer): MH1 1*; MH2 1*

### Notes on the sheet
- Variant
- Label Table
- Label Text
- 001
- 002
- ChangeMe!

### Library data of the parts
!PCB? = PCB: Manufacturer: Any; PartNumber: TIDA-01330; SymbolCreator: a0412235
FID1-FID3 = Fiducial: Fiducial mark.  There is nothing to buy or mount.; SymbolCreator: codlsc
Logo1 = TI_Logo: Texas Instrument Corporate Signature; SymbolCreator: codlsc
MH1 MH2 = Mounting Hole (Imperial) with Pads: PCB Mounting Hole; Manufacturer: Any; SymbolCreator: a0412235
Pb-Free = Pb-Free: SymbolCreator: a0412235

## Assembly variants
001: not fitted FID1 FID2 FID3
